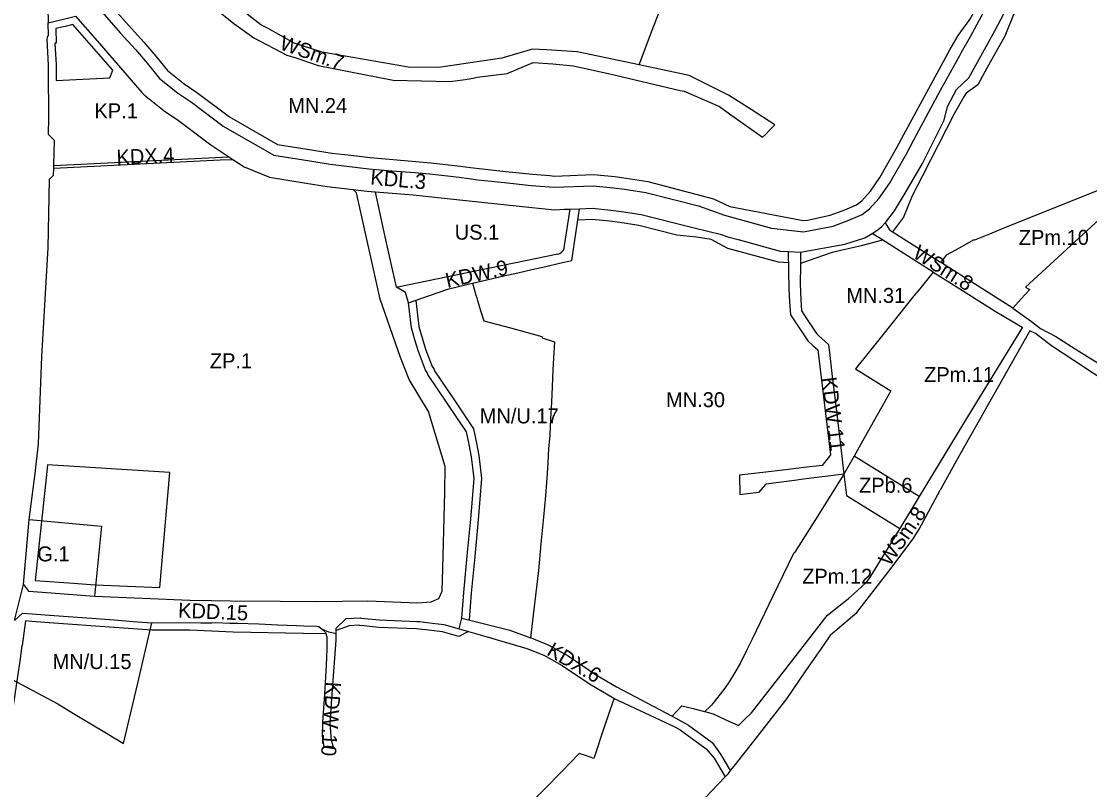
# Model space of a CAD drawing. Extents: x 7431080 to 7433370, y 5546450 to 5548428.
# Drawn here: x 7431991 to 7432562, y 5547100 to 5547511 of the extents above; entities that cross this region are included whole.
import ezdxf

# ---------------------------------------------------------------- set-up
doc = ezdxf.new("R2010")
doc.units = 0
for name, color, linetype in [('Linie Rozgraniczajace', 7, 'Continuous'), ('nieprzekraczalna linia zabudowy', 7, 'Continuous'), ('oznaczenia_przeznaczen', 7, 'Continuous')]:
    doc.layers.add(name, color=color, linetype=linetype)

msp = doc.modelspace()

# ---------------------------------------------------------------- linework, layer by layer
at = {"layer": 'Linie Rozgraniczajace'}
for p, q in [((7432005.58, 5547450.15), (7432005.71, 5547458.98)), ((7432008.68, 5547446.92), (7432005.58, 5547450.15)), ((7432008.37, 5547433.6), (7432101.94, 5547438.24)), ((7432005.32, 5547389.48), (7432005.99, 5547426.31)), ((7432005.99, 5547426.31), (7432008.25, 5547428.39)), ((7432002.03, 5547331.44), (7432005.32, 5547389.48)), ((7432407.75, 5547387.23), (7432407.62, 5547380.08)), ((7432407.62, 5547380.08), (7432407.45, 5547370.18)), ((7432478.6, 5547376.59), (7432475.01, 5547372.09)), ((7432478.6, 5547376.59), (7432487.59, 5547370.91)), ((7432232.22, 5547370.66), (7432234.09, 5547364.28)), ((7432407.45, 5547370.18), (7432407.85, 5547361.91)), ((7432475.01, 5547372.09), (7432471.43, 5547367.6)), ((7432487.59, 5547370.91), (7432511.74, 5547355.69)), ((7432468.34, 5547363.8), (7432450.99, 5547342.12)), ((7432471.43, 5547367.6), (7432468.34, 5547363.8)), ((7432407.85, 5547361.91), (7432408.14, 5547355.74)), ((7432408.14, 5547355.74), (7432409.75, 5547353.32)), ((7432409.75, 5547353.32), (7432416.18, 5547343.68)), ((7432526.34, 5547347.03), (7432495.03, 5547295.95)), ((7432416.18, 5547343.68), (7432417.26, 5547342.71)), ((7432417.26, 5547342.71), (7432422.63, 5547337.84)), ((7432450.99, 5547342.12), (7432437.11, 5547324.78)), ((7432530.34, 5547345.11), (7432491.03, 5547275.67)), ((7432422.63, 5547337.84), (7432422.83, 5547336.12)), ((7432422.83, 5547336.12), (7432423.14, 5547333.5)), ((7432000.17, 5547284.65), (7432002.03, 5547331.44)), ((7432423.14, 5547333.5), (7432424.66, 5547320.76)), ((7432437.11, 5547324.78), (7432455.89, 5547313.05)), ((7432424.66, 5547320.76), (7432426.18, 5547308.03)), ((7432455.89, 5547313.05), (7432441.7, 5547287.74)), ((7432426.18, 5547308.03), (7432429.21, 5547282.56)), ((7432495.03, 5547295.95), (7432471.1, 5547256.41)), ((7431998.46, 5547268.78), (7432000.17, 5547284.65)), ((7432441.7, 5547287.74), (7432436.31, 5547278.13)), ((7432429.21, 5547282.56), (7432430.9, 5547268.47)), ((7432436.31, 5547278.13), (7432430.9, 5547268.47)), ((7432471.1, 5547256.41), (7432436.31, 5547278.13)), ((7432491.03, 5547275.67), (7432482.42, 5547259.91)), ((7431995.16, 5547244.22), (7431998.46, 5547268.78)), ((7432430.9, 5547268.47), (7432409.34, 5547265.78)), ((7432389.13, 5547263.16), (7432385.17, 5547258.69)), ((7432404.39, 5547265.12), (7432389.13, 5547263.16)), ((7432409.34, 5547265.78), (7432404.39, 5547265.12)), ((7432385.17, 5547258.69), (7432375.16, 5547257.41)), ((7431992.07, 5547209.36), (7431995.16, 5547244.22)), ((7432450.2, 5547222.3), (7432445.07, 5547213.87)), ((7431987.26, 5547190.2), (7431992.07, 5547209.36)), ((7432445.07, 5547213.87), (7432442.82, 5547210.44))]:
    msp.add_line(p, q, dxfattribs=at)
for points in [[(7432321.38, 5547487.39), (7432328.05, 5547504.99), (7432334.72, 5547522.59), (7432351.22, 5547521.65), (7432379.78, 5547581.8), (7432407.04, 5547639.25)], [(7432440.7, 5547407.28), (7432444.63, 5547410.31), (7432449.78, 5547416.07), (7432455.2, 5547423.95), (7432464.31, 5547439.87), (7432468.3, 5547447.36), (7432482.61, 5547473.81), (7432492.81, 5547492.45), (7432493.84, 5547494.24), (7432498.62, 5547502.57), (7432512.77, 5547529.21), (7432519.57, 5547542.25), (7432520.68, 5547544.37), (7432522.9, 5547548.87), (7432524.02, 5547551.13), (7432527.88, 5547558.92), (7432535.55, 5547572.92), (7432538.43, 5547578.18), (7432540.35, 5547581.69), (7432541.31, 5547583.45), (7432553.31, 5547602.02), (7432554.79, 5547604.33), (7432559.96, 5547612.73), (7432566.3, 5547622.84)], [(7432448.53, 5547398.86), (7432450.95, 5547400.7), (7432452.97, 5547402.89), (7432453.29, 5547403.24), (7432457.88, 5547409.28), (7432463.71, 5547418.69), (7432472.86, 5547434.68), (7432484.51, 5547457.87), (7432486.28, 5547465.16), (7432491.17, 5547474.28), (7432497.66, 5547480.48), (7432502.29, 5547488.87), (7432511.59, 5547505.67), (7432526.59, 5547534.1), (7432528.92, 5547538.55), (7432528.98, 5547538.67), (7432537.97, 5547555.41), (7432551.75, 5547580.08), (7432563.79, 5547599.35)], [(7432005.55, 5547546.28), (7432005.23, 5547517.84), (7432005.39, 5547509.93), (7432013.55, 5547511.88), (7432019.96, 5547513.41), (7432031.57, 5547500.29), (7432055.49, 5547472.7)], [(7432005.55, 5547546.28), (7432014.94, 5547536.67), (7432031.83, 5547518.22), (7432043.81, 5547504.57), (7432051.97, 5547495.61), (7432058.36, 5547488.24), (7432064.88, 5547480.17)], [(7432321.38, 5547487.39), (7432288.19, 5547494.38), (7432271.81, 5547495.5), (7432264.27, 5547495.78), (7432247.98, 5547490.91), (7432214.17, 5547486.01), (7432197.88, 5547486.15), (7432192.94, 5547487), (7432151.81, 5547494.19), (7432136.9, 5547498.95), (7432122.92, 5547506.87), (7432119.08, 5547508.81), (7432089.1, 5547532.34), (7432084.17, 5547536.1), (7432078.89, 5547543.36), (7432073.69, 5547549.39)], [(7432094.52, 5547517.65), (7432104.67, 5547509.61), (7432115.3, 5547501.82), (7432132.94, 5547492.62), (7432137.74, 5547491.13), (7432145.13, 5547488.63), (7432149.68, 5547487.1), (7432189.89, 5547479.13), (7432220.17, 5547478.45), (7432227.13, 5547479.37), (7432229.44, 5547479.66), (7432232.67, 5547480.25), (7432234.67, 5547480.8), (7432250.71, 5547482.81), (7432264.64, 5547488.71), (7432275.27, 5547487.88), (7432286.16, 5547486.9), (7432291.01, 5547485.79), (7432305.75, 5547482.64), (7432343.24, 5547473.77), (7432345.38, 5547473.37), (7432364.32, 5547465.09), (7432369.68, 5547461.28), (7432387.32, 5547448.66), (7432388.92, 5547450.21), (7432391.56, 5547452.91), (7432393.63, 5547455.02)], [(7432005.71, 5547458.98), (7432005.59, 5547484.47), (7432005.57, 5547487.3), (7432005.22, 5547494.24), (7432004.86, 5547501.17), (7432005.2, 5547502.94), (7432005.52, 5547502.95), (7432005.39, 5547509.93)], [(7432640.78, 5547500.83), (7432633.11, 5547497.24), (7432631.07, 5547485.28), (7432629.04, 5547473.31), (7432624.91, 5547466.56), (7432620.78, 5547459.81), (7432609.32, 5547453.22), (7432601.93, 5547449.18), (7432596.03, 5547440.08), (7432590.13, 5547430.98), (7432579.76, 5547426.12), (7432569.39, 5547421.26), (7432543.12, 5547410.71), (7432516.84, 5547400.15), (7432508.77, 5547396.91), (7432500.7, 5547393.67), (7432500.07, 5547393.54), (7432492.82, 5547389.56), (7432485.57, 5547385.58), (7432484.07, 5547383.7), (7432482.57, 5547381.81)], [(7432393.63, 5547455.02), (7432393.88, 5547455.34), (7432381.3, 5547463.52), (7432369.14, 5547471.11), (7432348.06, 5547481.74), (7432321.38, 5547487.39)], [(7432064.88, 5547480.17), (7432074.44, 5547472.49), (7432081.92, 5547467.38), (7432098.93, 5547454.66), (7432125.95, 5547439.04), (7432145.26, 5547436), (7432156.13, 5547434.29), (7432166.5, 5547433.05), (7432176.87, 5547431.82), (7432189.18, 5547430.79), (7432201.49, 5547429.76), (7432209.31, 5547429.1), (7432217.2, 5547428.18), (7432225.09, 5547427.26), (7432230.34, 5547426.59), (7432235.11, 5547425.98), (7432249.41, 5547424.46), (7432263.7, 5547422.95), (7432275.99, 5547421.92)], [(7432055.49, 5547472.7), (7432056.74, 5547471.31), (7432067.29, 5547462.84), (7432074.94, 5547457.62), (7432092.31, 5547444.63), (7432101.94, 5547438.24), (7432104.05, 5547436.84), (7432110.14, 5547432.8), (7432123.77, 5547427.24), (7432143.39, 5547424.15), (7432154.49, 5547422.4), (7432168.51, 5547420.73), (7432175.66, 5547419.88), (7432180.35, 5547419.49), (7432200.49, 5547417.8), (7432223.64, 5547415.35), (7432262.38, 5547411.25), (7432276.31, 5547409.93)], [(7432008.25, 5547428.39), (7432008.33, 5547432.1), (7432008.37, 5547433.6), (7432008.68, 5547446.92)], [(7432008.33, 5547432.1), (7432097.32, 5547436.51), (7432104.05, 5547436.84)], [(7432592.52, 5547429.36), (7432583.24, 5547420.08), (7432573.95, 5547410.8), (7432528.05, 5547368.4), (7432529.17, 5547367.84), (7432530.29, 5547367.29), (7432525.74, 5547362.3), (7432521.19, 5547357.31)], [(7432149.06, 5547200.38), (7432176.25, 5547200.76), (7432202.88, 5547199.64), (7432210.19, 5547200.14), (7432214.28, 5547201.96), (7432216.05, 5547205.81), (7432216.4, 5547218.12), (7432217.38, 5547258.62), (7432217.67, 5547272.63), (7432208.74, 5547301.92), (7432198.31, 5547319.04), (7432193.8, 5547330.83), (7432182.8, 5547362.05), (7432170.14, 5547418.91), (7432168.51, 5547420.73)], [(7432275.99, 5547421.92), (7432296.76, 5547422.73), (7432307.61, 5547421.65), (7432313.58, 5547420.88), (7432324.87, 5547419.15), (7432353.09, 5547411.98), (7432367.09, 5547407)], [(7432152.71, 5547122.52), (7432158.18, 5547121.65), (7432156.89, 5547126.19), (7432156.08, 5547135.19), (7432157.25, 5547150.67), (7432159.39, 5547179.58), (7432159.37, 5547183.11), (7432159.32, 5547186.02), (7432164.61, 5547191.22), (7432172.18, 5547191.63), (7432172.69, 5547191.41), (7432174.49, 5547191.29), (7432182.49, 5547190.49), (7432202.48, 5547189.65), (7432204.08, 5547189.59), (7432207.81, 5547189.13), (7432216.92, 5547188.06), (7432225.1, 5547185.7), (7432226.58, 5547191.49), (7432227.61, 5547205.11), (7432229.46, 5547224.7), (7432231.3, 5547244.29), (7432233.07, 5547266.13), (7432232.38, 5547271.96), (7432231.7, 5547277.79), (7432230.44, 5547284.25), (7432229.04, 5547291.1), (7432218.75, 5547306.47), (7432208.45, 5547321.84), (7432208.06, 5547322.84), (7432207.1, 5547324.05), (7432203.29, 5547334), (7432201.48, 5547340.33), (7432199.66, 5547346.67), (7432198.03, 5547360.07), (7432196.34, 5547365.68), (7432191.62, 5547368.46), (7432185.96, 5547393.85), (7432180.31, 5547419.24), (7432180.35, 5547419.49)], [(7432276.31, 5547409.93), (7432281.38, 5547410.13), (7432284.4, 5547410.24), (7432289.49, 5547410.44), (7432296.4, 5547410.71), (7432306.25, 5547409.73), (7432311.9, 5547409), (7432322.48, 5547407.38), (7432350.13, 5547400.35)], [(7432277.83, 5547386.18), (7432278.99, 5547386.42), (7432280.08, 5547387.46), (7432281.18, 5547388.49), (7432282.87, 5547399.92), (7432284.4, 5547410.24)], [(7432278.86, 5547381.28), (7432285.38, 5547382.77), (7432287.7, 5547398.37), (7432289.49, 5547410.44)], [(7432367.09, 5547407), (7432392.14, 5547400.03), (7432409.33, 5547398), (7432425.12, 5547401.12), (7432433.54, 5547404.23), (7432440.7, 5547407.28)], [(7432350.13, 5547400.35), (7432358.82, 5547398.19), (7432364.65, 5547396.74)], [(7432364.65, 5547396.74), (7432368.73, 5547395.43), (7432374.3, 5547393.91), (7432396.78, 5547387.78), (7432401.06, 5547387.56), (7432407.75, 5547387.23), (7432431.43, 5547391.45), (7432442.1, 5547394.81), (7432446.01, 5547397.27), (7432448.53, 5547398.86)], [(7432452.97, 5547402.89), (7432455.3, 5547399.2), (7432482.57, 5547381.81)], [(7432478.6, 5547376.59), (7432451.08, 5547393.94), (7432446.01, 5547397.27)], [(7432401.06, 5547387.56), (7432401.24, 5547377.47)], [(7432277.83, 5547386.18), (7432254.55, 5547381.29), (7432234.51, 5547377.17), (7432192.32, 5547368.53), (7432191.62, 5547368.46)], [(7432198.03, 5547360.07), (7432208.81, 5547363.84), (7432219.59, 5547367.61), (7432232.22, 5547370.66), (7432249.07, 5547374.5), (7432256.56, 5547376.21), (7432264.05, 5547377.91), (7432271.46, 5547379.59), (7432278.86, 5547381.28)], [(7432521.19, 5547357.31), (7432489.46, 5547377.42), (7432482.57, 5547381.81)], [(7432401.24, 5547377.47), (7432401.41, 5547367.48), (7432401.83, 5547360.62), (7432402.25, 5547353.76), (7432406.92, 5547346.74), (7432411.6, 5547339.72), (7432414.27, 5547337.32), (7432416.94, 5547334.91), (7432420.29, 5547306.81), (7432423.64, 5547278.71), (7432419.24, 5547273.12), (7432409.53, 5547271.96), (7432399.81, 5547270.81), (7432387.44, 5547269.34), (7432375.07, 5547267.87)], [(7432234.09, 5547364.28), (7432234.5, 5547362.84), (7432234.91, 5547361.41), (7432236.58, 5547355.98), (7432238.26, 5547350.55), (7432252.5, 5547346.67)], [(7432511.74, 5547355.69), (7432526.13, 5547347.13), (7432526.34, 5547347.03)], [(7432521.19, 5547357.31), (7432531.2, 5547350.06), (7432536.02, 5547346.35), (7432544.15, 5547342.07), (7432556.5, 5547334.3), (7432560.85, 5547331.53), (7432585.82, 5547316.39)], [(7432252.5, 5547346.67), (7432269.35, 5547342.09), (7432269.55, 5547341.38), (7432276.02, 5547339.29), (7432275.88, 5547336.38), (7432275.73, 5547333.46), (7432275.29, 5547324.29), (7432274.84, 5547315.13), (7432274.43, 5547306.91), (7432274, 5547298.06), (7432273.57, 5547289.21), (7432273.25, 5547285.68), (7432272.93, 5547282.15), (7432272.46, 5547274.26), (7432271.99, 5547266.38), (7432271.61, 5547261.58), (7432271.22, 5547256.78), (7432270.69, 5547251.11), (7432270.16, 5547245.43), (7432268.83, 5547231.15), (7432267.51, 5547216.86), (7432265.44, 5547199.05), (7432263.33, 5547180.9)], [(7432663.63, 5547294.23), (7432654.79, 5547295.76), (7432635.74, 5547299.66), (7432623.93, 5547302.1), (7432615.72, 5547302.09), (7432611.11, 5547302.66), (7432606.5, 5547303.22), (7432598.99, 5547304.95), (7432595.07, 5547306.12), (7432591.15, 5547307.28), (7432583.92, 5547309.9), (7432574.27, 5547315.75), (7432553.87, 5547329.22), (7432541.98, 5547337.16), (7432533.37, 5547343.74), (7432530.34, 5547345.11)], [(7432430.9, 5547268.47), (7432417.79, 5547247.57), (7432404.69, 5547226.67), (7432404.33, 5547226.34), (7432403.96, 5547226.02), (7432392.92, 5547203.12), (7432381.89, 5547180.23), (7432378.64, 5547173.69), (7432375.39, 5547167.14), (7432372.48, 5547162.27)], [(7432375.07, 5547267.87), (7432375.16, 5547257.41)], [(7432430.9, 5547268.47), (7432432.25, 5547257.09), (7432460.71, 5547239.45)], [(7432423.78, 5547182.58), (7432437.83, 5547194.46), (7432454.4, 5547215.8), (7432467.89, 5547233.91), (7432471.09, 5547239.03), (7432482.42, 5547259.91)], [(7432471.1, 5547256.41), (7432460.71, 5547239.45), (7432450.2, 5547222.3)], [(7431995.16, 5547244.22), (7432033.79, 5547240.61), (7432030.16, 5547203.25)], [(7431992.07, 5547209.36), (7431994.75, 5547205.82), (7432006.95, 5547204.96), (7432030.16, 5547203.25), (7432081.07, 5547201.02), (7432092.6, 5547200.88), (7432102.79, 5547200.77), (7432129.32, 5547200.51), (7432149.06, 5547200.38)], [(7432338.97, 5547138.97), (7432341.12, 5547141.3), (7432344.16, 5547144.6), (7432350.25, 5547143.06), (7432356.38, 5547141.56), (7432356.58, 5547141.5), (7432360.94, 5547140.2), (7432367.69, 5547137.09), (7432374.43, 5547133.99), (7432377.96, 5547137.41), (7432381.5, 5547140.83), (7432401.7, 5547166.8), (7432421.89, 5547192.78), (7432427.53, 5547197.25), (7432433.17, 5547201.72), (7432438.16, 5547206.23), (7432442.82, 5547210.44)], [(7431987.26, 5547190.2), (7431991.61, 5547194.02), (7431996.84, 5547193.65), (7432006.09, 5547192.99), (7432023.49, 5547191.71), (7432040.89, 5547190.43), (7432050.86, 5547189.69), (7432060.83, 5547188.95), (7432081.02, 5547189.02), (7432086.97, 5547188.95), (7432092.93, 5547188.88), (7432094.88, 5547189.01), (7432102.42, 5547188.78), (7432106.42, 5547188.66), (7432117.96, 5547188.31), (7432128.08, 5547187.88), (7432138.21, 5547187.45), (7432142.09, 5547187.22), (7432149.05, 5547187.07), (7432150.13, 5547186.96), (7432151.99, 5547185.41)], [(7431983.01, 5547160.16), (7431996.75, 5547152.83), (7432010.48, 5547145.51), (7432018.88, 5547140.48), (7432027.28, 5547135.45), (7432036.46, 5547129.95), (7432045.63, 5547124.44), (7432053.23, 5547156.7), (7432060.83, 5547188.95)], [(7432226.58, 5547191.49), (7432252.22, 5547184.99), (7432263.33, 5547180.9), (7432263.58, 5547180.81)], [(7432151.99, 5547185.41), (7432153.57, 5547183.67), (7432154.31, 5547181.41), (7432154.35, 5547174.91), (7432154.14, 5547170.48), (7432153.93, 5547166.04), (7432153.02, 5547150.78), (7432152.11, 5547135.52), (7432151.9, 5547128.49), (7432152.71, 5547122.52)], [(7432159.37, 5547183.11), (7432155.46, 5547183.92), (7432151.99, 5547185.41)], [(7432225.1, 5547185.7), (7432238.8, 5547181.86), (7432261.36, 5547175.24)], [(7432263.58, 5547180.81), (7432273.08, 5547177.04), (7432283.34, 5547171.19), (7432298.12, 5547161.32), (7432309.23, 5547154.62), (7432338.97, 5547138.97), (7432340.99, 5547137.91), (7432347.8, 5547134.23), (7432360.39, 5547124.83), (7432364.91, 5547118.67), (7432370.13, 5547109.85)], [(7432423.78, 5547182.58), (7432419.92, 5547176.98), (7432410.04, 5547162.65), (7432400.16, 5547148.32), (7432385.65, 5547129.72), (7432372.71, 5547113.14), (7432371.12, 5547111.11)], [(7432261.36, 5547175.24), (7432270.47, 5547171.62), (7432280.18, 5547166.08), (7432294.9, 5547156.26), (7432307.91, 5547148.55), (7432308.09, 5547148.46), (7432340.77, 5547133.11), (7432343.33, 5547131.72), (7432357.29, 5547121.47), (7432361.56, 5547116.47), (7432367.41, 5547106.59)], [(7432372.48, 5547162.27), (7432369.56, 5547157.4), (7432367.17, 5547154.05), (7432364.78, 5547150.71), (7432362.66, 5547148.17), (7432360.53, 5547145.63), (7432359.98, 5547144.86), (7432359.43, 5547144.09), (7432356.58, 5547141.5)], [(7432307.49, 5547147.27), (7432302.75, 5547133.04), (7432297.22, 5547116.4), (7432293.29, 5547117.71), (7432289.35, 5547119.02), (7432279.94, 5547109.38), (7432270.53, 5547099.73), (7432255.89, 5547084.97)], [(7432308.09, 5547148.46), (7432307.49, 5547147.27)], [(7432371.12, 5547111.11), (7432370.13, 5547109.85), (7432369, 5547108.4), (7432368.36, 5547107.58), (7432367.41, 5547106.59), (7432359.99, 5547098.79), (7432351.61, 5547089.99), (7432349.01, 5547087.53)]]:
    msp.add_lwpolyline(points, dxfattribs=at)
at = {"layer": 'nieprzekraczalna linia zabudowy'}
msp.add_line((7432230.05, 5547184.31), (7432224.93, 5547181.58), dxfattribs=at)
for points in [[(7432491.98, 5547503.05), (7432498.28, 5547511.7), (7432504.11, 5547522.15), (7432515.11, 5547546.68), (7432518.58, 5547553.68)], [(7432010.74, 5547549.56), (7432019.3, 5547540.79), (7432036.3, 5547522.23), (7432048.28, 5547508.57), (7432056.46, 5547499.6), (7432062.96, 5547492.09), (7432069.14, 5547484.44), (7432078.02, 5547477.31), (7432085.41, 5547472.26), (7432102.24, 5547459.68), (7432127.99, 5547444.79), (7432146.19, 5547441.93), (7432156.95, 5547440.23), (7432167.21, 5547439.02), (7432177.48, 5547437.79), (7432201.99, 5547435.74), (7432209.91, 5547435.07), (7432225.82, 5547433.22), (7432231.1, 5547432.54), (7432235.81, 5547431.94), (7432250.04, 5547430.44), (7432264.27, 5547428.92), (7432273.56, 5547428.15), (7432276.13, 5547427.93)], [(7432531.68, 5547530.87), (7432522.17, 5547515.54), (7432516.87, 5547502.82), (7432507.54, 5547485.97), (7432502.47, 5547476.78), (7432496.2, 5547472.31), (7432495.04, 5547470.22), (7432495.04, 5547470.22), (7432495.04, 5547470.22), (7432489.83, 5547461.25), (7432472.94, 5547427.95), (7432467.43, 5547417.38), (7432462.83, 5547405.88), (7432456.95, 5547398.15)], [(7432009.45, 5547506.79), (7432009.59, 5547499.08), (7432008.97, 5547499.06), (7432009.57, 5547487.42), (7432009.59, 5547484.49), (7432009.62, 5547479.07)], [(7432039.96, 5547484.51), (7432028.56, 5547497.65), (7432018.55, 5547508.96), (7432014.48, 5547507.99), (7432009.45, 5547506.79)], [(7432459.06, 5547442.78), (7432463.01, 5547450.2), (7432477.34, 5547476.68), (7432487.58, 5547495.39), (7432489.52, 5547498.77), (7432491.98, 5547503.05)], [(7432009.62, 5547479.07), (7432038.24, 5547480.48), (7432039.96, 5547484.51)], [(7432361.17, 5547415.81), (7432369.84, 5547411.66), (7432409.09, 5547404.07), (7432411.32, 5547404.34), (7432423.49, 5547406.91), (7432431.32, 5547409.81), (7432437.64, 5547412.5), (7432440.53, 5547414.72), (7432445.05, 5547419.78), (7432450.12, 5547427.15), (7432459.06, 5547442.78)], [(7432276.13, 5547427.93), (7432296.94, 5547428.74), (7432308.29, 5547427.62), (7432314.42, 5547426.82), (7432326.07, 5547425.04), (7432361.17, 5547415.81)], [(7432341.51, 5547396.35), (7432321.28, 5547401.49), (7432311.06, 5547403.06), (7432305.57, 5547403.77), (7432296.22, 5547404.7), (7432288.59, 5547404.4)], [(7432368.76, 5547389.2), (7432359.89, 5547393.89), (7432352.02, 5547395.16), (7432341.51, 5547396.35)], [(7432451.53, 5547393.66), (7432440.04, 5547390.6), (7432424.6, 5547387.1), (7432407.64, 5547381.12)], [(7432401.16, 5547381.55), (7432395.83, 5547381.82), (7432368.76, 5547389.2)], [(7432201.9, 5547361.42), (7432203.59, 5547347.47), (7432205.33, 5547341.44), (7432207.09, 5547335.27), (7432210.62, 5547326.05), (7432211.57, 5547324.85), (7432212.02, 5547323.7), (7432222.07, 5547308.7), (7432232.8, 5547292.67), (7432234.36, 5547285.03), (7432235.65, 5547278.41), (7432236.36, 5547272.43), (7432237.09, 5547266.2), (7432235.28, 5547243.94), (7432233.44, 5547224.32), (7432231.6, 5547204.77), (7432230.52, 5547190.49)], [(7432005, 5547273.43), (7432004.42, 5547268.06), (7431998.29, 5547211.58)], [(7432070.48, 5547269.34), (7432005, 5547273.43)], [(7432065.02, 5547207.73), (7432070.48, 5547269.34)], [(7431998.29, 5547211.58), (7432018.96, 5547210.09), (7432030.51, 5547209.24), (7432065.02, 5547207.73)], [(7431993.22, 5547189.9), (7431991.48, 5547176.73), (7431991.24, 5547176.76), (7431990.13, 5547168.46), (7431989.01, 5547160.16), (7431987.57, 5547150.55), (7431986.12, 5547140.94), (7431984.64, 5547131.68), (7431982.63, 5547119.11)], [(7432153.8, 5547182.97), (7432141.93, 5547183.22), (7432104.34, 5547183.98), (7432104.34, 5547183.98), (7432104.34, 5547183.98), (7432081, 5547185.02), (7432060.69, 5547184.95), (7432040.6, 5547186.44), (7432005.8, 5547189), (7431996.57, 5547189.66), (7431993.22, 5547189.9)], [(7432224.93, 5547181.58), (7432216.13, 5547184.13), (7432207.33, 5547185.16), (7432203.76, 5547185.6), (7432202.32, 5547185.65), (7432182.21, 5547186.5), (7432174.16, 5547187.3), (7432171.74, 5547187.46), (7432171.46, 5547187.59), (7432166.34, 5547187.31), (7432159.34, 5547184.8)]]:
    msp.add_lwpolyline(points, dxfattribs=at)

# ---------------------------------------------------------------- texts
at = {"layer": 'oznaczenia_przeznaczen'}
for s, rotation, p in [('WSm.7', 340.5903, (7432128.53, 5547495.94)), ('KDX.4', 2.5234, (7432042.05, 5547433.92)), ('KDL.3', 354.9822, (7432177.4, 5547423.38)), ('WSm.8', 327.6123, (7432467.1, 5547384.81)), ('KDW.9', 12.7862, (7432218.83, 5547367.96)), ('KDW.11', 276.8868, (7432418.9, 5547319.97)), ('WSm.8', 55.2686, (7432455.33, 5547218.68)), ('KDD.15', 357.6816, (7432074.68, 5547191.68)), ('KDX.6', 329.5967, (7432271.42, 5547172.04)), ('KDX.6', 329.5967, (7432271.42, 5547172.04)), ('KDW.10', 265.904, (7432154.06, 5547157.6))]:
    msp.add_text(s, height=8, rotation=rotation, dxfattribs=at).set_placement(p)
for s, p in [('KP.1', (7432030.1, 5547458.8)), ('MN.24', (7432133.71, 5547461.61)), ('US.1', (7432222.76, 5547393.89)), ('ZPm.10', (7432524.41, 5547391.11)), ('MN.31', (7432432.15, 5547360.07)), ('ZP.1', (7432091.79, 5547325.07)), ('ZPm.11', (7432473.76, 5547317.7)), ('MN.30', (7432335.78, 5547304.29)), ('MN/U.17', (7432236.12, 5547295.6)), ('ZPb.6', (7432438.98, 5547258.5)), ('G.1', (7431999.51, 5547221.79)), ('G.1', (7431999.51, 5547221.79)), ('ZPm.12', (7432408.57, 5547209.83)), ('MN/U.15', (7432007.68, 5547164.18))]:
    msp.add_text(s, height=8, dxfattribs=at).set_placement(p)

doc.saveas('drawing.dxf')
